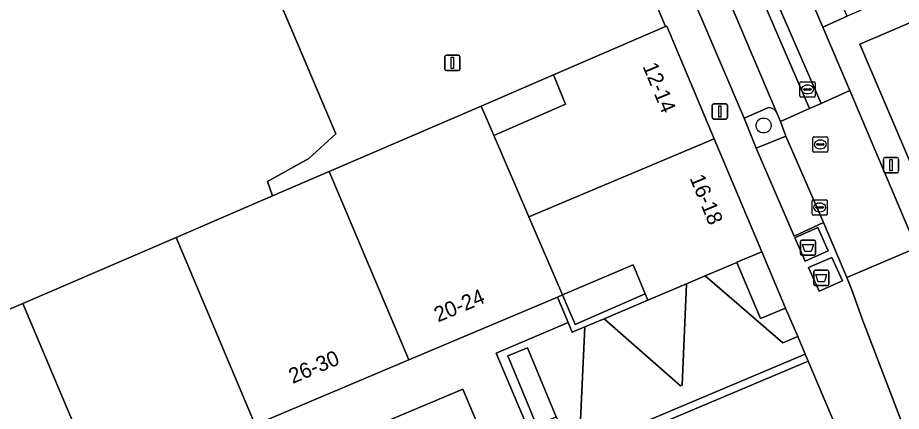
# Model space of a CAD drawing. Extents: x 161771 to 163125, y 382475 to 383179.
# Drawn here: x 161888.7 to 161946.5, y 383006.8 to 383032.6 of the extents above; entities that cross this region are included whole.
import ezdxf

# ---------------------------------------------------------------- set-up
doc = ezdxf.new("R2010")
doc.units = 0
for name, color, linetype in [('IMGEO_Afval_apart_plaats', 7, 'Continuous'), ('IMGEO_Boom', 7, 'Continuous'), ('IMGEO_Erf', 7, 'Continuous'), ('IMGEO_Groenvoorziening', 7, 'Continuous'), ('IMGEO_Kolk', 7, 'Continuous'), ('IMGEO_Lichtmast', 7, 'Continuous'), ('IMGEO_Muur', 7, 'Continuous'), ('IMGEO_Pand', 7, 'Continuous'), ('IMGEO_Pand_nummerreeks', 7, 'Continuous'), ('IMGEO_Parkeervlak_open', 7, 'Continuous'), ('IMGEO_Rijbaan_lokaal_gesloten', 7, 'Continuous'), ('IMGEO_Rijbaan_lokaal_open', 7, 'Continuous'), ('IMGEO_Terreindeel_onvherhard', 7, 'Continuous'), ('IMGEO_Terreindeel_open', 7, 'Continuous'), ('IMGEO_Voetpad_gesloten', 7, 'Continuous'), ('IMGEO_Voetpad_op_trap', 7, 'Continuous'), ('IMGEO_Voetpad_open', 7, 'Continuous')]:
    doc.layers.add(name, color=color, linetype=linetype)

msp = doc.modelspace()

# ---------------------------------------------------------------- linework, layer by layer
at = {"layer": 'IMGEO_Afval_apart_plaats'}
for p, q in [((161939.947, 383017.142), (161939.947, 383017.942)), ((161939.947, 383017.942), (161939.947, 383017.142)), ((161940.047, 383018.042), (161940.837, 383018.042)), ((161940.837, 383018.042), (161940.047, 383018.042)), ((161940.937, 383017.942), (161940.937, 383017.142)), ((161940.937, 383017.142), (161940.937, 383017.942)), ((161940.837, 383017.042), (161940.047, 383017.042)), ((161940.047, 383017.042), (161940.837, 383017.042)), ((161940.814, 383015.161), (161940.814, 383015.961)), ((161940.814, 383015.961), (161940.814, 383015.161)), ((161940.914, 383016.061), (161941.704, 383016.061)), ((161941.704, 383016.061), (161940.914, 383016.061)), ((161941.804, 383015.961), (161941.804, 383015.161)), ((161941.804, 383015.161), (161941.804, 383015.961)), ((161941.704, 383015.061), (161940.914, 383015.061)), ((161940.914, 383015.061), (161941.704, 383015.061))]:
    msp.add_line(p, q, dxfattribs=at)
for points in [[(161940.09, 383017.756), (161940.794, 383017.756), (161940.645, 383017.286), (161940.239, 383017.286), (161940.09, 383017.756)], [(161940.957, 383015.775), (161941.661, 383015.775), (161941.512, 383015.305), (161941.106, 383015.305), (161940.957, 383015.775)]]:
    msp.add_lwpolyline(points, dxfattribs=at)
for centre, start, end in [((161940.047, 383017.942), 90, 180), ((161940.047, 383017.942), 90, 180), ((161940.837, 383017.942), 0, 90), ((161940.837, 383017.942), 360, 90), ((161940.047, 383017.142), 180, 270), ((161940.047, 383017.142), 180, 270), ((161940.837, 383017.142), 270, 0), ((161940.837, 383017.142), 270, 0), ((161940.914, 383015.961), 90, 180), ((161940.914, 383015.961), 90, 180), ((161941.704, 383015.961), 0, 90), ((161941.704, 383015.961), 360, 90), ((161940.914, 383015.161), 180, 270), ((161940.914, 383015.161), 180, 270), ((161941.704, 383015.161), 270, 0), ((161941.704, 383015.161), 270, 0)]:
    msp.add_arc(centre, 0.1, start, end, dxfattribs=at)
at = {"layer": 'IMGEO_Boom'}
msp.add_circle((161937.532, 383025.532), 0.489, dxfattribs=at)
at = {"layer": 'IMGEO_Erf'}
msp.add_lwpolyline([(161921.637, 383054.403), (161909.758, 383049.317), (161901.122, 383045.61), (161902.178, 383043.614), (161900.645, 383042.96), (161902.469, 383040.319), (161903.159, 383039.175), (161904.545, 383036.296), (161906.154, 383032.954), (161907.022, 383030.902), (161909.528, 383024.978), (161907.765, 383023.383), (161905.069, 383021.86), (161905.402, 383020.934), (161909.106, 383022.529), (161919.044, 383026.807), (161923.778, 383028.845), (161931.107, 383032.001)], close=True, dxfattribs=at)
at = {"layer": 'IMGEO_Groenvoorziening'}
for points in [[(161956.251, 383036.199), (161950.431, 383033.665), (161943.83, 383030.854), (161947.833, 383021.506), (161948.931, 383022.196)], [(161937.822, 383026.684), (161936.27, 383026.002), (161937.054, 383024.052), (161938.989, 383024.836), (161938.63, 383025.789)], [(161938.63, 383025.789), (161938.378, 383026.395)]]:
    msp.add_lwpolyline(points, dxfattribs=at)
for points in [[(161935.784, 383016.579), (161933.717, 383015.703), (161938.787, 383011.318), (161939.77, 383011.722), (161938.978, 383013.584), (161938.974, 383013.582), (161937.339, 383012.911)], [(161932.492, 383015.184), (161929.95, 383014.107), (161927.092, 383012.893), (161932.095, 383008.511), (161932.194, 383008.55)], [(161925.838, 383012.36), (161925.01, 383012.008), (161925.01, 383012.009), (161924.747, 383012.641), (161920.038, 383010.64), (161922.126, 383005.689), (161922.662, 383005.927), (161920.789, 383010.467), (161922.072, 383010.99), (161923.966, 383006.479), (161924.037, 383006.31), (161924.46, 383005.353), (161925.518, 383005.799)], [(161913.699, 383004.252), (161917.003, 383005.658), (161917.835, 383003.727), (161919.484, 383004.406), (161917.846, 383008.276), (161912.88, 383006.184)]]:
    msp.add_lwpolyline(points, close=True, dxfattribs=at)
msp.add_arc((161937.908, 383026.17), 0.521, 25.55549, 99.51511, dxfattribs=at)
at = {"layer": 'IMGEO_Kolk'}
for p, q in [((161939.909, 383027.469), (161939.909, 383028.321)), ((161939.984, 383028.395), (161940.836, 383028.395)), ((161940.91, 383028.321), (161940.91, 383027.469)), ((161940.168, 383027.889), (161940.168, 383027.901)), ((161940.606, 383027.852), (161940.208, 383027.852)), ((161940.211, 383027.938), (161940.609, 383027.938)), ((161940.397, 383028.175), (161940.422, 383028.175)), ((161940.652, 383027.901), (161940.652, 383027.889)), ((161940.836, 383027.395), (161939.984, 383027.395)), ((161940.42, 383027.615), (161940.395, 383027.615)), ((161940.746, 383023.868), (161940.746, 383024.72)), ((161940.821, 383024.794), (161941.673, 383024.794)), ((161941.005, 383024.288), (161941.005, 383024.3)), ((161941.443, 383024.251), (161941.045, 383024.251)), ((161941.048, 383024.337), (161941.446, 383024.337)), ((161941.234, 383024.574), (161941.259, 383024.574)), ((161941.489, 383024.3), (161941.489, 383024.288)), ((161941.747, 383024.72), (161941.747, 383023.868)), ((161941.673, 383023.794), (161940.821, 383023.794)), ((161941.257, 383024.014), (161941.232, 383024.014)), ((161940.704, 383019.749), (161940.704, 383020.601)), ((161940.779, 383020.675), (161941.631, 383020.675)), ((161941.006, 383020.218), (161941.404, 383020.218)), ((161941.192, 383020.455), (161941.217, 383020.455)), ((161941.705, 383020.601), (161941.705, 383019.749)), ((161941.631, 383019.675), (161940.779, 383019.675)), ((161940.963, 383020.169), (161940.963, 383020.181)), ((161941.401, 383020.132), (161941.003, 383020.132)), ((161941.215, 383019.895), (161941.19, 383019.895)), ((161941.447, 383020.181), (161941.447, 383020.169))]:
    msp.add_line(p, q, dxfattribs=at)
for points in [[(161939.909, 383027.469), (161939.909, 383028.321)], [(161939.984, 383028.395), (161940.836, 383028.395)], [(161940.91, 383028.321), (161940.91, 383027.469)], [(161940.836, 383027.395), (161939.984, 383027.395)], [(161940.746, 383023.868), (161940.746, 383024.72)], [(161940.821, 383024.794), (161941.673, 383024.794)], [(161941.747, 383024.72), (161941.747, 383023.868)], [(161941.673, 383023.794), (161940.821, 383023.794)], [(161940.704, 383019.749), (161940.704, 383020.601)], [(161940.779, 383020.675), (161941.631, 383020.675)], [(161941.705, 383020.601), (161941.705, 383019.749)], [(161941.631, 383019.675), (161940.779, 383019.675)]]:
    msp.add_lwpolyline(points, dxfattribs=at)
for centre, radius, start, end in [((161939.986, 383028.319), 0.0765, 91.55205, 178.44795), ((161939.986, 383028.319), 0.0765, 91.55205, 178.44795), ((161940.834, 383028.319), 0.0765, 1.55205, 88.44795), ((161940.834, 383028.319), 0.0765, 1.55205, 88.44795), ((161940.208, 383027.898), 0.0403, 85.87752, 175.75265), ((161940.205, 383027.888), 0.0366, 178.93798, 274.71019), ((161940.609, 383027.895), 0.043, 264.86636, 352.45326), ((161940.613, 383027.9), 0.0386, 1.73085, 96.63898), ((161939.986, 383027.471), 0.0765, 181.55205, 268.44795), ((161939.986, 383027.471), 0.0765, 181.55205, 268.44795), ((161940.834, 383027.471), 0.0765, 271.55205, 358.44795), ((161940.834, 383027.471), 0.0765, 271.55205, 358.44795), ((161940.823, 383024.718), 0.0765, 91.55205, 178.44795), ((161940.823, 383024.718), 0.0765, 91.55205, 178.44795), ((161941.045, 383024.297), 0.0403, 85.87752, 175.75265), ((161941.042, 383024.287), 0.0366, 178.93798, 274.71019), ((161941.446, 383024.294), 0.043, 264.86636, 352.45326), ((161941.45, 383024.299), 0.0386, 1.73085, 96.63898), ((161941.671, 383024.718), 0.0765, 1.55205, 88.44795), ((161941.671, 383024.718), 0.0765, 1.55205, 88.44795), ((161940.823, 383023.87), 0.0765, 181.55205, 268.44795), ((161940.823, 383023.87), 0.0765, 181.55205, 268.44795), ((161941.671, 383023.87), 0.0765, 271.55205, 358.44795), ((161941.671, 383023.87), 0.0765, 271.55205, 358.44795), ((161940.781, 383020.599), 0.0765, 91.55205, 178.44795), ((161940.781, 383020.599), 0.0765, 91.55205, 178.44795), ((161941.003, 383020.178), 0.0403, 85.87752, 175.75265), ((161941.408, 383020.18), 0.0386, 1.73085, 96.63898), ((161941.629, 383020.599), 0.0765, 1.55205, 88.44795), ((161941.629, 383020.599), 0.0765, 1.55205, 88.44795), ((161940.781, 383019.751), 0.0765, 181.55205, 268.44795), ((161940.781, 383019.751), 0.0765, 181.55205, 268.44795), ((161941, 383020.168), 0.0366, 178.93798, 274.71019), ((161941.404, 383020.175), 0.043, 264.86636, 352.45326), ((161941.629, 383019.751), 0.0765, 271.55205, 358.44795), ((161941.629, 383019.751), 0.0765, 271.55205, 358.44795)]:
    msp.add_arc(centre, radius, start, end, dxfattribs=at)
for centre, major_axis, ratio, start_param, end_param in [((161940.396, 383027.895), (-0.387, 0.002), 0.722429, 4.712389, 7.853982), ((161940.421, 383027.895), (-0.39, 0.002), 0.717154, 1.570796, 4.712389), ((161941.233, 383024.294), (-0.387, 0.002), 0.722429, 4.712389, 7.853982), ((161941.258, 383024.294), (-0.39, 0.002), 0.717154, 1.570796, 4.712389), ((161941.191, 383020.175), (-0.387, 0.002), 0.722429, 4.712389, 7.853982), ((161941.216, 383020.175), (-0.39, 0.002), 0.717154, 1.570796, 4.712389)]:
    msp.add_ellipse(centre, major_axis=major_axis, ratio=ratio, start_param=start_param, end_param=end_param, dxfattribs=at)
at = {"layer": 'IMGEO_Lichtmast'}
for p, q in [((161916.67, 383029.228), (161916.67, 383030.028)), ((161916.67, 383030.028), (161916.67, 383029.228)), ((161916.77, 383030.128), (161917.56, 383030.128)), ((161917.56, 383030.128), (161916.77, 383030.128)), ((161917.66, 383030.028), (161917.66, 383029.228)), ((161917.66, 383029.228), (161917.66, 383030.028)), ((161917.56, 383029.128), (161916.77, 383029.128)), ((161916.77, 383029.128), (161917.56, 383029.128)), ((161934.174, 383026.055), (161934.174, 383026.855)), ((161934.174, 383026.855), (161934.174, 383026.055)), ((161934.274, 383026.955), (161935.064, 383026.955)), ((161935.064, 383026.955), (161934.274, 383026.955)), ((161935.164, 383026.855), (161935.164, 383026.055)), ((161935.164, 383026.055), (161935.164, 383026.855)), ((161935.064, 383025.955), (161934.274, 383025.955)), ((161934.274, 383025.955), (161935.064, 383025.955)), ((161945.384, 383022.536), (161945.384, 383023.336)), ((161945.384, 383023.336), (161945.384, 383022.536)), ((161945.484, 383023.436), (161946.274, 383023.436)), ((161946.274, 383023.436), (161945.484, 383023.436)), ((161946.374, 383023.336), (161946.374, 383022.536)), ((161946.374, 383022.536), (161946.374, 383023.336)), ((161946.274, 383022.436), (161945.484, 383022.436)), ((161945.484, 383022.436), (161946.274, 383022.436))]:
    msp.add_line(p, q, dxfattribs=at)
for points in [[(161917.09, 383030.003), (161917.24, 383030.003), (161917.24, 383029.253), (161917.09, 383029.253), (161917.09, 383030.003)], [(161934.594, 383026.83), (161934.744, 383026.83), (161934.744, 383026.08), (161934.594, 383026.08), (161934.594, 383026.83)], [(161945.804, 383023.311), (161945.954, 383023.311), (161945.954, 383022.561), (161945.804, 383022.561), (161945.804, 383023.311)]]:
    msp.add_lwpolyline(points, dxfattribs=at)
for centre, start, end in [((161916.77, 383030.028), 90, 180), ((161916.77, 383030.028), 90, 180), ((161917.56, 383030.028), 0, 90), ((161917.56, 383030.028), 360, 90), ((161916.77, 383029.228), 180, 270), ((161916.77, 383029.228), 180, 270), ((161917.56, 383029.228), 270, 0), ((161917.56, 383029.228), 270, 0), ((161934.274, 383026.855), 90, 180), ((161934.274, 383026.855), 90, 180), ((161935.064, 383026.855), 0, 90), ((161935.064, 383026.855), 360, 90), ((161934.274, 383026.055), 180, 270), ((161934.274, 383026.055), 180, 270), ((161935.064, 383026.055), 270, 0), ((161935.064, 383026.055), 270, 0), ((161945.484, 383023.336), 90, 180), ((161945.484, 383023.336), 90, 180), ((161946.274, 383023.336), 0, 90), ((161946.274, 383023.336), 360, 90), ((161945.484, 383022.536), 180, 270), ((161945.484, 383022.536), 180, 270), ((161946.274, 383022.536), 270, 0), ((161946.274, 383022.536), 270, 0)]:
    msp.add_arc(centre, 0.1, start, end, dxfattribs=at)
at = {"layer": 'IMGEO_Muur'}
msp.add_lwpolyline([(161907.022, 383030.902), (161906.154, 383032.954), (161904.545, 383036.296), (161903.159, 383039.175), (161902.469, 383040.319)], dxfattribs=at)
for points in [[(161927.092, 383012.893), (161929.95, 383014.107), (161929.782, 383014.51), (161925.431, 383012.618), (161925.203, 383012.519), (161925.088, 383012.786), (161924.746, 383013.579), (161924.371, 383014.449), (161924.052, 383014.313), (161924.747, 383012.641), (161925.01, 383012.009), (161925.01, 383012.008), (161925.838, 383012.36)], [(161940.453, 383010.118), (161940.256, 383010.581), (161924.749, 383004.042), (161924.943, 383003.577), (161925.008, 383003.604)]]:
    msp.add_lwpolyline(points, close=True, dxfattribs=at)
at = {"layer": 'IMGEO_Pand'}
for points in [[(161931.196, 383032.039), (161931.107, 383032.001), (161923.778, 383028.845), (161924.576, 383026.936), (161919.876, 383024.877), (161920.042, 383024.492), (161922.172, 383019.55), (161934.303, 383024.653)], [(161922.172, 383019.55), (161920.042, 383024.492), (161919.876, 383024.877), (161919.761, 383025.144), (161919.419, 383025.937), (161919.044, 383026.807), (161909.106, 383022.529), (161914.315, 383010.199), (161924.052, 383014.313), (161924.371, 383014.449)], [(161934.303, 383024.653), (161922.172, 383019.55), (161924.371, 383014.449), (161928.987, 383016.412), (161929.782, 383014.51), (161929.95, 383014.107), (161932.492, 383015.184), (161933.717, 383015.703), (161935.784, 383016.579), (161935.79, 383016.582), (161937.41, 383017.268)], [(161909.106, 383022.529), (161905.402, 383020.934), (161899.078, 383018.211), (161904.258, 383005.95), (161914.315, 383010.199)], [(161899.078, 383018.211), (161889.05, 383013.894), (161894.202, 383001.701), (161904.258, 383005.95)], [(161889.05, 383013.894), (161885.425, 383012.333), (161882.579, 383011.108), (161881.301, 383010.558), (161879.023, 383009.577), (161884.145, 382997.452), (161894.202, 383001.701)]]:
    msp.add_lwpolyline(points, close=True, dxfattribs=at)
at = {"layer": 'IMGEO_Parkeervlak_open'}
for points in [[(161938.378, 383026.395), (161933.342, 383038.281)], [(161933.122, 383037.696), (161931.546, 383037.041), (161936.27, 383026.002), (161937.822, 383026.684)]]:
    msp.add_lwpolyline(points, dxfattribs=at)
msp.add_lwpolyline([(161938.989, 383024.836), (161937.054, 383024.052), (161939.541, 383018.297), (161941.449, 383019.179)], close=True, dxfattribs=at)
msp.add_arc((161937.908, 383026.17), 0.521, 25.55549, 99.51511, dxfattribs=at)
at = {"layer": 'IMGEO_Rijbaan_lokaal_gesloten'}
msp.add_lwpolyline([(161942.283, 383005.799), (161940.453, 383010.118), (161925.008, 383003.604), (161925.291, 383002.943), (161926.803, 382999.456), (161926.87, 382999.301), (161929.84, 383000.566), (161934.811, 383002.658)], close=True, dxfattribs=at)
at = {"layer": 'IMGEO_Rijbaan_lokaal_open'}
for points in [[(161922.387, 383069.775), (161923.152, 383070.063), (161929.185, 383055.447), (161935.336, 383040.651), (161941.307, 383026.98), (161943.177, 383027.812), (161941.403, 383031.963), (161932.608, 383052.538), (161924.683, 383072.01), (161920.07, 383070.029), (161920.306, 383069.44), (161927.275, 383052.464), (161927.918, 383050.884), (161932.616, 383039.884), (161933.342, 383038.281), (161938.378, 383026.395), (161938.63, 383025.789), (161940.535, 383026.637), (161934.585, 383040.452), (161928.401, 383055.201)], [(161922.387, 383069.775), (161928.401, 383055.201), (161934.585, 383040.452), (161940.535, 383026.637), (161941.307, 383026.98), (161935.336, 383040.651), (161929.185, 383055.447), (161923.152, 383070.063)], [(161943.177, 383027.812), (161941.307, 383026.98), (161940.535, 383026.637), (161938.63, 383025.789), (161938.989, 383024.836), (161941.449, 383019.179), (161942.983, 383015.58), (161947.533, 383017.528)]]:
    msp.add_lwpolyline(points, close=True, dxfattribs=at)
msp.add_lwpolyline([(161947.533, 383017.528), (161942.983, 383015.58), (161943.332, 383014.713), (161944.007, 383012.809), (161946.34, 383006.744), (161947.885, 383002.626), (161948.26, 383001.581), (161948.711, 383000.633), (161948.95, 383000), (161949.428, 382998.734), (161949.478, 382998.607), (161955.317, 382983.812), (161962.344, 382965.829), (161971.239, 382943.112), (161977.654, 382926.832), (161978.485, 382924.755), (161978.58, 382924.549)], dxfattribs=at)
at = {"layer": 'IMGEO_Terreindeel_onvherhard'}
msp.add_lwpolyline([(161885.425, 383012.333), (161889.05, 383013.894), (161899.078, 383018.211), (161905.402, 383020.934), (161905.069, 383021.86), (161907.765, 383023.383), (161909.528, 383024.978), (161907.022, 383030.902), (161906.154, 383032.954), (161904.545, 383036.296), (161903.159, 383039.175), (161902.469, 383040.319), (161899.808, 383038.481), (161896.636, 383043.073), (161893.159, 383048.107), (161891.383, 383046.881), (161889.767, 383045.765), (161893.237, 383040.742), (161890.429, 383038.802), (161887.827, 383037.005)], dxfattribs=at)
at = {"layer": 'IMGEO_Terreindeel_open'}
for points in [[(161924.576, 383026.936), (161923.778, 383028.845), (161919.044, 383026.807), (161919.419, 383025.937), (161919.761, 383025.144), (161919.876, 383024.877)], [(161929.782, 383014.51), (161928.987, 383016.412), (161924.371, 383014.449), (161924.746, 383013.579), (161925.088, 383012.786), (161925.203, 383012.519), (161925.431, 383012.618)]]:
    msp.add_lwpolyline(points, close=True, dxfattribs=at)
at = {"layer": 'IMGEO_Voetpad_gesloten'}
for points in [[(161941.084, 383018.858), (161939.579, 383018.182), (161940.265, 383016.656), (161941.766, 383017.34)], [(161940.472, 383016.238), (161941.172, 383014.689), (161942.694, 383015.376), (161942.009, 383016.893)]]:
    msp.add_lwpolyline(points, close=True, dxfattribs=at)
at = {"layer": 'IMGEO_Voetpad_op_trap'}
msp.add_lwpolyline([(161922.662, 383005.927), (161923.966, 383006.479), (161922.072, 383010.99), (161920.789, 383010.467)], close=True, dxfattribs=at)
at = {"layer": 'IMGEO_Voetpad_open'}
for points in [[(161913.394, 383074.196), (161914.126, 383072.74), (161914.277, 383072.549), (161918.153, 383063.602), (161918.783, 383062.147), (161922.059, 383054.584), (161921.944, 383054.534), (161921.637, 383054.403), (161931.107, 383032.001), (161931.196, 383032.039), (161934.303, 383024.653), (161937.41, 383017.268), (161938.978, 383013.584), (161939.77, 383011.722), (161940.256, 383010.581), (161940.453, 383010.118), (161942.283, 383005.799), (161945.407, 382998.406), (161948.531, 382991.013)], [(161923.916, 383073.896), (161924.683, 383072.01), (161932.608, 383052.538), (161941.403, 383031.963), (161942.996, 383032.682), (161937.106, 383046.256)], [(161949.428, 382998.734), (161948.95, 383000), (161948.711, 383000.633), (161948.26, 383001.581), (161947.885, 383002.626), (161946.34, 383006.744), (161944.007, 383012.809), (161943.332, 383014.713), (161942.983, 383015.58), (161941.449, 383019.179), (161939.541, 383018.297), (161937.054, 383024.052), (161936.27, 383026.002), (161931.546, 383037.041), (161930.708, 383039.055), (161932.616, 383039.884), (161927.918, 383050.884), (161925.988, 383050.092), (161925.161, 383052.062), (161918.501, 383068.252), (161917.694, 383070.178), (161919.632, 383070.986)], [(162006.759, 383061.373), (162004.206, 383064.476), (162002.297, 383063.547), (162003.558, 383060.66), (161996.747, 383057.684), (161997.348, 383056.289), (161996.575, 383055.947), (161996.563, 383055.975), (161996.324, 383055.871), (161992.1, 383054.032), (161987.468, 383052.016), (161982.836, 383050), (161978.204, 383047.984), (161973.572, 383045.967), (161968.941, 383043.951), (161968.251, 383043.651), (161964.307, 383041.938), (161959.674, 383039.926), (161955.04, 383037.913), (161950.407, 383035.901), (161942.996, 383032.682), (161941.403, 383031.963), (161943.177, 383027.812), (161947.533, 383017.528)], [(161948.972, 383018.847), (161947.833, 383021.506), (161943.83, 383030.854), (161950.431, 383033.665), (161956.251, 383036.199), (161969.026, 383041.761), (161969.484, 383041.961), (161999.765, 383055.155)], [(161924.749, 383004.042), (161940.256, 383010.581), (161939.77, 383011.722), (161938.787, 383011.318), (161933.717, 383015.703), (161932.492, 383015.184), (161932.194, 383008.55), (161932.095, 383008.511), (161927.092, 383012.893), (161925.838, 383012.36), (161925.518, 383005.799)], [(161922.126, 383005.689), (161920.038, 383010.64), (161924.747, 383012.641), (161924.052, 383014.313), (161914.315, 383010.199), (161904.258, 383005.95)]]:
    msp.add_lwpolyline(points, dxfattribs=at)
for points in [[(161939.579, 383018.182), (161941.084, 383018.858), (161941.766, 383017.34), (161940.265, 383016.656)], [(161937.41, 383017.268), (161935.79, 383016.582), (161935.784, 383016.579), (161937.339, 383012.911), (161938.974, 383013.582), (161938.978, 383013.584)], [(161941.172, 383014.689), (161940.472, 383016.238), (161942.009, 383016.893), (161942.694, 383015.376)], [(161913.699, 383004.252), (161912.88, 383006.184), (161917.846, 383008.276), (161919.484, 383004.406), (161917.835, 383003.727), (161917.003, 383005.658)]]:
    msp.add_lwpolyline(points, close=True, dxfattribs=at)

# ---------------------------------------------------------------- texts
at = {"layer": 'IMGEO_Pand_nummerreeks'}
for s, rotation, p in [('12-14', 292.62016, (161929.599, 383029.408)), ('16-18', 292.62016, (161932.678, 383022.091)), ('20-24', 22.70632, (161916.225, 383012.643)), ('26-30', 22.70632, (161906.71, 383008.623))]:
    msp.add_text(s, height=1, rotation=rotation, dxfattribs=at).set_placement(p)

doc.saveas('drawing.dxf')
